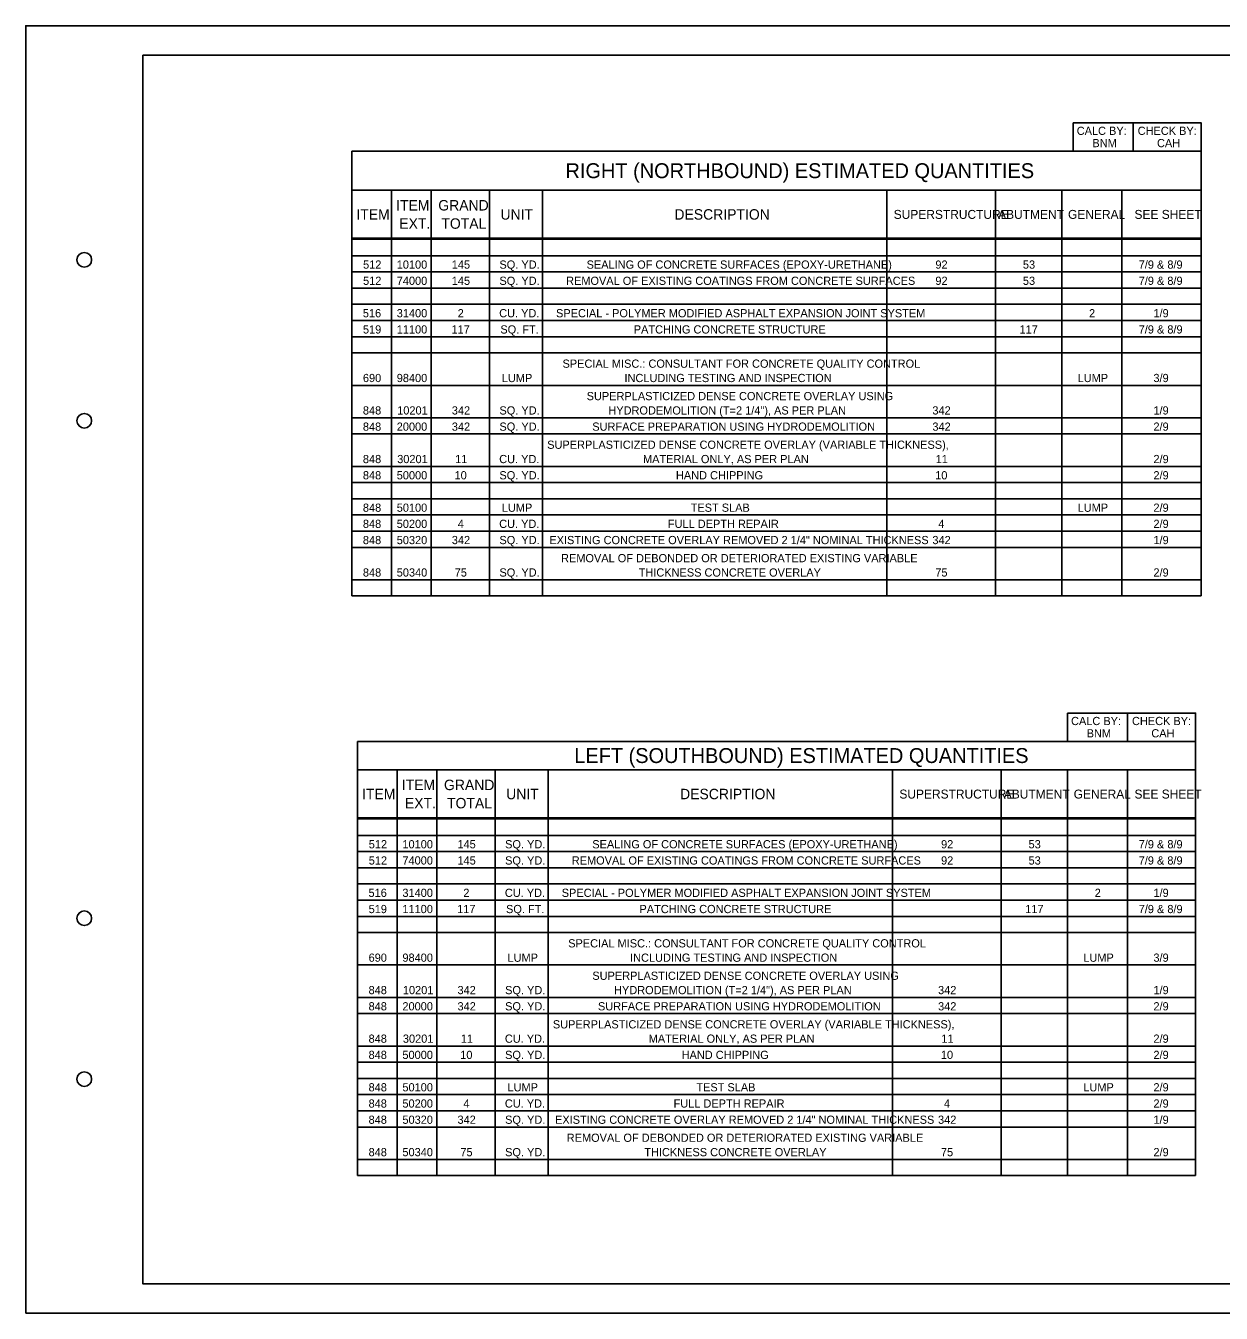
# Model space of a CAD drawing. Extents: x -17.7 to 16.3, y -7.1 to 14.9.
# Drawn here: x -17.72 to 2.71, y -7.05 to 14.95 of the extents above; entities that cross this region are included whole.
import ezdxf

# ---------------------------------------------------------------- set-up
doc = ezdxf.new("R2010")
doc.units = 0
for name, color, linetype in [('SH_Border', 7, 'Continuous'), ('SH_Cut_Line', 7, 'Continuous'), ('SH_Text', 7, 'Continuous')]:
    doc.layers.add(name, color=color, linetype=linetype)

msp = doc.modelspace()

# ---------------------------------------------------------------- linework, layer by layer
at = {"layer": 'SH_Border'}
msp.add_lwpolyline([(-15.715, 14.446), (15.785, 14.446), (15.785, -6.554), (-15.715, -6.554)], close=True, dxfattribs=at)
for centre in [(-16.715, 10.946), (-16.715, 8.196), (-16.715, -0.304), (-16.715, -3.054)]:
    msp.add_circle(centre, 0.125, dxfattribs=at)
at = {"layer": 'SH_Cut_Line'}
msp.add_lwpolyline([(-17.715, -7.054), (16.285, -7.054), (16.285, 14.946), (-17.715, 14.946)], close=True, dxfattribs=at)
at = {"layer": 'SH_Text'}
for p, q in [((1.201, 12.802), (1.201, 13.287)), ((-12.145, 12.802), (2.364, 12.802)), ((-12.145, 12.802), (-12.145, 11.298)), ((2.364, 12.802), (2.364, 11.298)), ((-12.145, 12.138), (2.364, 12.138)), ((-11.466, 12.138), (-11.466, 11.316)), ((-10.788, 12.138), (-10.788, 11.316)), ((-9.791, 12.138), (-9.791, 11.316)), ((-8.891, 12.138), (-8.891, 11.316)), ((-3.008, 12.138), (-3.008, 11.316)), ((-1.152, 12.138), (-1.152, 11.316)), ((-0.017, 12.138), (-0.017, 11.316)), ((1.007, 12.138), (1.007, 11.316)), ((-12.145, 11.316), (2.364, 11.316)), ((-12.145, 11.316), (-12.145, 5.202)), ((-12.145, 11.298), (2.364, 11.298)), ((-11.466, 11.298), (-11.466, 5.202)), ((-10.788, 11.298), (-10.788, 5.202)), ((-9.791, 11.298), (-9.791, 5.202)), ((-8.891, 11.298), (-8.891, 5.202)), ((-3.008, 11.298), (-3.008, 5.202)), ((-1.152, 11.298), (-1.152, 5.202)), ((-0.017, 11.298), (-0.017, 5.202)), ((1.007, 11.298), (1.007, 5.202)), ((2.364, 11.316), (2.364, 5.202)), ((-12.145, 11.016), (2.364, 11.016)), ((-12.145, 10.739), (2.364, 10.739)), ((-12.145, 10.462), (2.364, 10.462)), ((-12.145, 10.186), (2.364, 10.186)), ((-12.145, 9.909), (2.364, 9.909)), ((-12.145, 9.632), (2.364, 9.632)), ((-12.145, 9.355), (2.364, 9.355)), ((-12.145, 8.801), (2.364, 8.801)), ((-12.145, 8.247), (2.364, 8.247)), ((-12.145, 7.971), (2.364, 7.971)), ((-12.145, 7.417), (2.364, 7.417)), ((-12.145, 7.14), (2.364, 7.14)), ((-12.145, 6.863), (2.364, 6.863)), ((-12.145, 6.586), (2.364, 6.586)), ((-12.145, 6.309), (2.364, 6.309)), ((-12.145, 6.032), (2.364, 6.032)), ((-12.145, 5.479), (2.364, 5.479)), ((-12.145, 5.202), (2.364, 5.202)), ((1.104, 2.718), (1.104, 3.202)), ((-12.048, 2.718), (2.267, 2.718)), ((-12.048, 2.718), (-12.048, 1.393)), ((2.267, 2.718), (2.267, 1.393)), ((-12.048, 2.233), (2.267, 2.233)), ((-11.369, 2.233), (-11.369, 1.412)), ((-10.691, 2.233), (-10.691, 1.412)), ((-9.694, 2.233), (-9.694, 1.412)), ((-8.794, 2.233), (-8.794, 1.412)), ((-2.911, 2.233), (-2.911, 1.412)), ((-1.056, 2.233), (-1.056, 1.412)), ((0.08, 2.233), (0.08, 1.412)), ((1.104, 2.233), (1.104, 1.412)), ((-12.048, 1.412), (2.267, 1.412)), ((-12.048, 1.412), (-12.048, -4.703)), ((-12.048, 1.393), (2.267, 1.393)), ((-11.369, 1.393), (-11.369, -4.703)), ((-10.691, 1.393), (-10.691, -4.703)), ((-9.694, 1.393), (-9.694, -4.703)), ((-8.794, 1.393), (-8.794, -4.703)), ((-2.911, 1.393), (-2.911, -4.703)), ((-1.056, 1.393), (-1.056, -4.703)), ((0.08, 1.393), (0.08, -4.703)), ((1.104, 1.393), (1.104, -4.703)), ((2.267, 1.412), (2.267, -4.703)), ((-12.048, 1.112), (2.267, 1.112)), ((-12.048, 0.835), (2.267, 0.835)), ((-12.048, 0.558), (2.267, 0.558)), ((-12.048, 0.281), (2.267, 0.281)), ((-12.048, 0.004), (2.267, 0.004)), ((-12.048, -0.273), (2.267, -0.273)), ((-12.048, -0.55), (2.267, -0.55)), ((-12.048, -1.103), (2.267, -1.103)), ((-12.048, -1.657), (2.267, -1.657)), ((-12.048, -1.934), (2.267, -1.934)), ((-12.048, -2.488), (2.267, -2.488)), ((-12.048, -2.765), (2.267, -2.765)), ((-12.048, -3.042), (2.267, -3.042)), ((-12.048, -3.318), (2.267, -3.318)), ((-12.048, -3.595), (2.267, -3.595)), ((-12.048, -3.872), (2.267, -3.872)), ((-12.048, -4.426), (2.267, -4.426)), ((-12.048, -4.703), (2.267, -4.703))]:
    msp.add_line(p, q, dxfattribs=at)
for points in [[(0.177, 13.287), (2.364, 13.287), (2.364, 12.802), (0.177, 12.802)], [(0.08, 3.202), (2.267, 3.202), (2.267, 2.718), (0.08, 2.718)]]:
    msp.add_lwpolyline(points, close=True, dxfattribs=at)

# ---------------------------------------------------------------- texts
for s, height, p in [('CALC BY:', 0.14, (0.238, 13.081)), ('CHECK BY:', 0.14, (1.279, 13.081)), ('BNM', 0.14, (0.505, 12.871)), ('CAH', 0.14, (1.609, 12.871)), ('RIGHT (NORTHBOUND) ESTIMATED QUANTITIES', 0.25473, (-8.495, 12.342)), ('ITEM', 0.1783, (-11.389, 11.789)), ('GRAND', 0.1783, (-10.668, 11.789)), ('ITEM', 0.1783, (-12.068, 11.633)), ('UNIT', 0.1783, (-9.606, 11.633)), ('DESCRIPTION', 0.17831, (-6.635, 11.633)), ('SUPERSTRUCTURE', 0.15284, (-2.889, 11.646)), ('ABUTMENT', 0.1528, (-1.105, 11.646)), ('GENERAL', 0.1528, (0.089, 11.646)), ('SEE SHEET', 0.1528, (1.224, 11.646)), ('EXT.', 0.1783, (-11.334, 11.477)), ('TOTAL', 0.1783, (-10.616, 11.477)), ('512', 0.1401, (-11.953, 10.795)), ('10100', 0.1401, (-11.378, 10.795)), ('145', 0.1401, (-10.438, 10.795)), ('SQ. YD.', 0.1401, (-9.624, 10.795)), ('SEALING OF CONCRETE SURFACES (EPOXY-URETHANE)', 0.1401, (-8.135, 10.795)), ('92', 0.1401, (-2.177, 10.795)), ('53', 0.1401, (-0.682, 10.795)), ('7/9 & 8/9', 0.1401, (1.296, 10.795)), ('512', 0.1401, (-11.953, 10.518)), ('74000', 0.1401, (-11.378, 10.518)), ('145', 0.1401, (-10.438, 10.518)), ('SQ. YD.', 0.1401, (-9.624, 10.518)), ('REMOVAL OF EXISTING COATINGS FROM CONCRETE SURFACES', 0.1401, (-8.485, 10.518)), ('92', 0.1401, (-2.177, 10.518)), ('53', 0.1401, (-0.682, 10.518)), ('7/9 & 8/9', 0.1401, (1.296, 10.518)), ('516', 0.1401, (-11.957, 9.964)), ('31400', 0.1401, (-11.378, 9.964)), ('2', 0.14, (-10.337, 9.964)), ('CU. YD.', 0.1401, (-9.628, 9.964)), ('SPECIAL - POLYMER MODIFIED ASPHALT EXPANSION JOINT SYSTEM', 0.1401, (-8.657, 9.964)), ('2', 0.14, (0.448, 9.964)), ('1/9', 0.1401, (1.548, 9.964)), ('519', 0.1401, (-11.955, 9.687)), ('11100', 0.1401, (-11.378, 9.687)), ('117', 0.1401, (-10.443, 9.687)), ('SQ. FT.', 0.1401, (-9.608, 9.687)), ('PATCHING CONCRETE STRUCTURE', 0.1401, (-7.329, 9.687)), ('117', 0.1401, (-0.739, 9.687)), ('7/9 & 8/9', 0.1401, (1.296, 9.687)), ('SPECIAL MISC.: CONSULTANT FOR CONCRETE QUALITY CONTROL', 0.1401, (-8.546, 9.102)), ('690', 0.1401, (-11.956, 8.857)), ('98400', 0.1401, (-11.378, 8.857)), ('LUMP', 0.1401, (-9.583, 8.857)), ('INCLUDING TESTING AND INSPECTION', 0.1401, (-7.488, 8.857)), ('LUMP', 0.1401, (0.253, 8.857)), ('3/9', 0.1401, (1.548, 8.857)), ('SUPERPLASTICIZED DENSE CONCRETE OVERLAY USING', 0.1401, (-8.134, 8.548)), ('848', 0.1401, (-11.956, 8.303)), ('10201', 0.1401, (-11.37, 8.303)), ('342', 0.1401, (-10.437, 8.303)), ('SQ. YD.', 0.1401, (-9.624, 8.303)), ('HYDRODEMOLITION (T=2 1/4"), AS PER PLAN', 0.1401, (-7.763, 8.303)), ('342', 0.1401, (-2.228, 8.303)), ('1/9', 0.1401, (1.548, 8.303)), ('848', 0.1401, (-11.956, 8.026)), ('20000', 0.1401, (-11.378, 8.026)), ('342', 0.1401, (-10.437, 8.026)), ('SQ. YD.', 0.1401, (-9.624, 8.026)), ('SURFACE PREPARATION USING HYDRODEMOLITION', 0.1401, (-8.038, 8.026)), ('342', 0.1401, (-2.228, 8.026)), ('2/9', 0.1401, (1.548, 8.026)), ('SUPERPLASTICIZED DENSE CONCRETE OVERLAY (VARIABLE THICKNESS),', 0.1401, (-8.808, 7.717)), ('848', 0.1401, (-11.956, 7.472)), ('30201', 0.1401, (-11.37, 7.472)), ('11', 0.1401, (-10.381, 7.472)), ('CU. YD.', 0.1401, (-9.628, 7.472)), ('MATERIAL ONLY, AS PER PLAN', 0.1401, (-7.171, 7.472)), ('11', 0.1401, (-2.172, 7.472)), ('2/9', 0.1401, (1.548, 7.472)), ('848', 0.1401, (-11.956, 7.195)), ('50000', 0.1401, (-11.378, 7.195)), ('10', 0.1401, (-10.39, 7.195)), ('SQ. YD.', 0.1401, (-9.624, 7.195)), ('HAND CHIPPING', 0.1401, (-6.609, 7.195)), ('10', 0.1401, (-2.18, 7.195)), ('2/9', 0.1401, (1.548, 7.195)), ('848', 0.1401, (-11.956, 6.641)), ('50100', 0.1401, (-11.378, 6.641)), ('LUMP', 0.1401, (-9.583, 6.641)), ('TEST SLAB', 0.1401, (-6.357, 6.641)), ('LUMP', 0.1401, (0.253, 6.641)), ('2/9', 0.1401, (1.548, 6.641)), ('848', 0.1401, (-11.956, 6.365)), ('50200', 0.1401, (-11.378, 6.365)), ('4', 0.14, (-10.336, 6.365)), ('CU. YD.', 0.1401, (-9.628, 6.365)), ('FULL DEPTH REPAIR', 0.1401, (-6.746, 6.365)), ('4', 0.14, (-2.127, 6.365)), ('2/9', 0.1401, (1.548, 6.365)), ('848', 0.1401, (-11.956, 6.088)), ('50320', 0.1401, (-11.378, 6.088)), ('342', 0.1401, (-10.437, 6.088)), ('SQ. YD.', 0.1401, (-9.624, 6.088)), ('EXISTING CONCRETE OVERLAY REMOVED 2 1/4" NOMINAL THICKNESS', 0.1401, (-8.771, 6.088)), ('342', 0.1401, (-2.228, 6.088)), ('1/9', 0.1401, (1.548, 6.088)), ('REMOVAL OF DEBONDED OR DETERIORATED EXISTING VARIABLE', 0.1401, (-8.571, 5.779)), ('848', 0.1401, (-11.956, 5.534)), ('50340', 0.1401, (-11.378, 5.534)), ('75', 0.1401, (-10.388, 5.534)), ('SQ. YD.', 0.1401, (-9.624, 5.534)), ('THICKNESS CONCRETE OVERLAY', 0.1401, (-7.245, 5.534)), ('75', 0.1401, (-2.178, 5.534)), ('2/9', 0.1401, (1.548, 5.534)), ('CALC BY:', 0.14, (0.141, 2.996)), ('CHECK BY:', 0.14, (1.182, 2.996)), ('BNM', 0.14, (0.408, 2.786)), ('CAH', 0.14, (1.512, 2.786)), ('LEFT (SOUTHBOUND) ESTIMATED QUANTITIES', 0.25473, (-8.345, 2.348)), ('ITEM', 0.1783, (-11.292, 1.885)), ('GRAND', 0.1783, (-10.571, 1.885)), ('ITEM', 0.1783, (-11.971, 1.729)), ('UNIT', 0.1783, (-9.509, 1.729)), ('DESCRIPTION', 0.17831, (-6.538, 1.729)), ('SUPERSTRUCTURE', 0.15284, (-2.792, 1.741)), ('ABUTMENT', 0.1528, (-1.008, 1.741)), ('GENERAL', 0.1528, (0.186, 1.741)), ('SEE SHEET', 0.1528, (1.224, 1.741)), ('EXT.', 0.1783, (-11.238, 1.573)), ('TOTAL', 0.1783, (-10.519, 1.573)), ('512', 0.1401, (-11.856, 0.89)), ('10100', 0.1401, (-11.281, 0.89)), ('145', 0.1401, (-10.341, 0.89)), ('SQ. YD.', 0.1401, (-9.527, 0.89)), ('SEALING OF CONCRETE SURFACES (EPOXY-URETHANE)', 0.1401, (-8.038, 0.89)), ('92', 0.1401, (-2.08, 0.89)), ('53', 0.1401, (-0.585, 0.89)), ('7/9 & 8/9', 0.1401, (1.296, 0.89)), ('512', 0.1401, (-11.856, 0.613)), ('74000', 0.1401, (-11.281, 0.613)), ('145', 0.1401, (-10.341, 0.613)), ('SQ. YD.', 0.1401, (-9.527, 0.613)), ('REMOVAL OF EXISTING COATINGS FROM CONCRETE SURFACES', 0.1401, (-8.388, 0.613)), ('92', 0.1401, (-2.08, 0.613)), ('53', 0.1401, (-0.585, 0.613)), ('7/9 & 8/9', 0.1401, (1.296, 0.613)), ('516', 0.1401, (-11.86, 0.06)), ('31400', 0.1401, (-11.281, 0.06)), ('2', 0.14, (-10.24, 0.06)), ('CU. YD.', 0.1401, (-9.531, 0.06)), ('SPECIAL - POLYMER MODIFIED ASPHALT EXPANSION JOINT SYSTEM', 0.1401, (-8.56, 0.06)), ('2', 0.14, (0.545, 0.06)), ('1/9', 0.1401, (1.548, 0.06)), ('519', 0.1401, (-11.858, -0.217)), ('11100', 0.1401, (-11.281, -0.217)), ('117', 0.1401, (-10.346, -0.217)), ('SQ. FT.', 0.1401, (-9.511, -0.217)), ('PATCHING CONCRETE STRUCTURE', 0.1401, (-7.232, -0.217)), ('117', 0.1401, (-0.642, -0.217)), ('7/9 & 8/9', 0.1401, (1.296, -0.217)), ('SPECIAL MISC.: CONSULTANT FOR CONCRETE QUALITY CONTROL', 0.1401, (-8.449, -0.803)), ('690', 0.1401, (-11.859, -1.048)), ('98400', 0.1401, (-11.281, -1.048)), ('LUMP', 0.1401, (-9.486, -1.048)), ('INCLUDING TESTING AND INSPECTION', 0.1401, (-7.392, -1.048)), ('LUMP', 0.1401, (0.35, -1.048)), ('3/9', 0.1401, (1.548, -1.048)), ('SUPERPLASTICIZED DENSE CONCRETE OVERLAY USING', 0.1401, (-8.037, -1.357)), ('848', 0.1401, (-11.859, -1.602)), ('10201', 0.1401, (-11.273, -1.602)), ('342', 0.1401, (-10.34, -1.602)), ('SQ. YD.', 0.1401, (-9.527, -1.602)), ('HYDRODEMOLITION (T=2 1/4"), AS PER PLAN', 0.1401, (-7.666, -1.602)), ('342', 0.1401, (-2.131, -1.602)), ('1/9', 0.1401, (1.548, -1.602)), ('848', 0.1401, (-11.859, -1.879)), ('20000', 0.1401, (-11.281, -1.879)), ('342', 0.1401, (-10.34, -1.879)), ('SQ. YD.', 0.1401, (-9.527, -1.879)), ('SURFACE PREPARATION USING HYDRODEMOLITION', 0.1401, (-7.941, -1.879)), ('342', 0.1401, (-2.131, -1.879)), ('2/9', 0.1401, (1.548, -1.879)), ('SUPERPLASTICIZED DENSE CONCRETE OVERLAY (VARIABLE THICKNESS),', 0.1401, (-8.711, -2.187)), ('848', 0.1401, (-11.859, -2.432)), ('30201', 0.1401, (-11.273, -2.432)), ('11', 0.1401, (-10.284, -2.432)), ('CU. YD.', 0.1401, (-9.531, -2.432)), ('MATERIAL ONLY, AS PER PLAN', 0.1401, (-7.074, -2.432)), ('11', 0.1401, (-2.075, -2.432)), ('2/9', 0.1401, (1.548, -2.432)), ('848', 0.1401, (-11.859, -2.709)), ('50000', 0.1401, (-11.281, -2.709)), ('10', 0.1401, (-10.293, -2.709)), ('SQ. YD.', 0.1401, (-9.527, -2.709)), ('HAND CHIPPING', 0.1401, (-6.512, -2.709)), ('10', 0.1401, (-2.083, -2.709)), ('2/9', 0.1401, (1.548, -2.709)), ('848', 0.1401, (-11.859, -3.263)), ('50100', 0.1401, (-11.281, -3.263)), ('LUMP', 0.1401, (-9.486, -3.263)), ('TEST SLAB', 0.1401, (-6.26, -3.263)), ('LUMP', 0.1401, (0.35, -3.263)), ('2/9', 0.1401, (1.548, -3.263)), ('848', 0.1401, (-11.859, -3.54)), ('50200', 0.1401, (-11.281, -3.54)), ('4', 0.14, (-10.239, -3.54)), ('CU. YD.', 0.1401, (-9.531, -3.54)), ('FULL DEPTH REPAIR', 0.1401, (-6.649, -3.54)), ('4', 0.14, (-2.03, -3.54)), ('2/9', 0.1401, (1.548, -3.54)), ('848', 0.1401, (-11.859, -3.817)), ('50320', 0.1401, (-11.281, -3.817)), ('342', 0.1401, (-10.34, -3.817)), ('SQ. YD.', 0.1401, (-9.527, -3.817)), ('EXISTING CONCRETE OVERLAY REMOVED 2 1/4" NOMINAL THICKNESS', 0.1401, (-8.674, -3.817)), ('342', 0.1401, (-2.131, -3.817)), ('1/9', 0.1401, (1.548, -3.817)), ('REMOVAL OF DEBONDED OR DETERIORATED EXISTING VARIABLE', 0.1401, (-8.474, -4.125)), ('848', 0.1401, (-11.859, -4.371)), ('50340', 0.1401, (-11.281, -4.371)), ('75', 0.1401, (-10.291, -4.371)), ('SQ. YD.', 0.1401, (-9.527, -4.371)), ('THICKNESS CONCRETE OVERLAY', 0.1401, (-7.149, -4.371)), ('75', 0.1401, (-2.082, -4.371)), ('2/9', 0.1401, (1.548, -4.371))]:
    msp.add_text(s, height=height, dxfattribs=at).set_placement(p)

doc.saveas('drawing.dxf')
